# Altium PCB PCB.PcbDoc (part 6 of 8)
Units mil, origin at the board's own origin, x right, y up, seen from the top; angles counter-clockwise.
Board outline 11229.24 x 7764.43 mil, 14 copper layers (Top Layer, GND1, Signal 1, GND2, Signal 2, GND3, Singal 3, Power 1, GND4, Power 2, GND5, Power 3, GND6, Bottom Layer), stack 91.892 mil thick; 877 components, 305 nets, 2660 pads, 2851 vias.
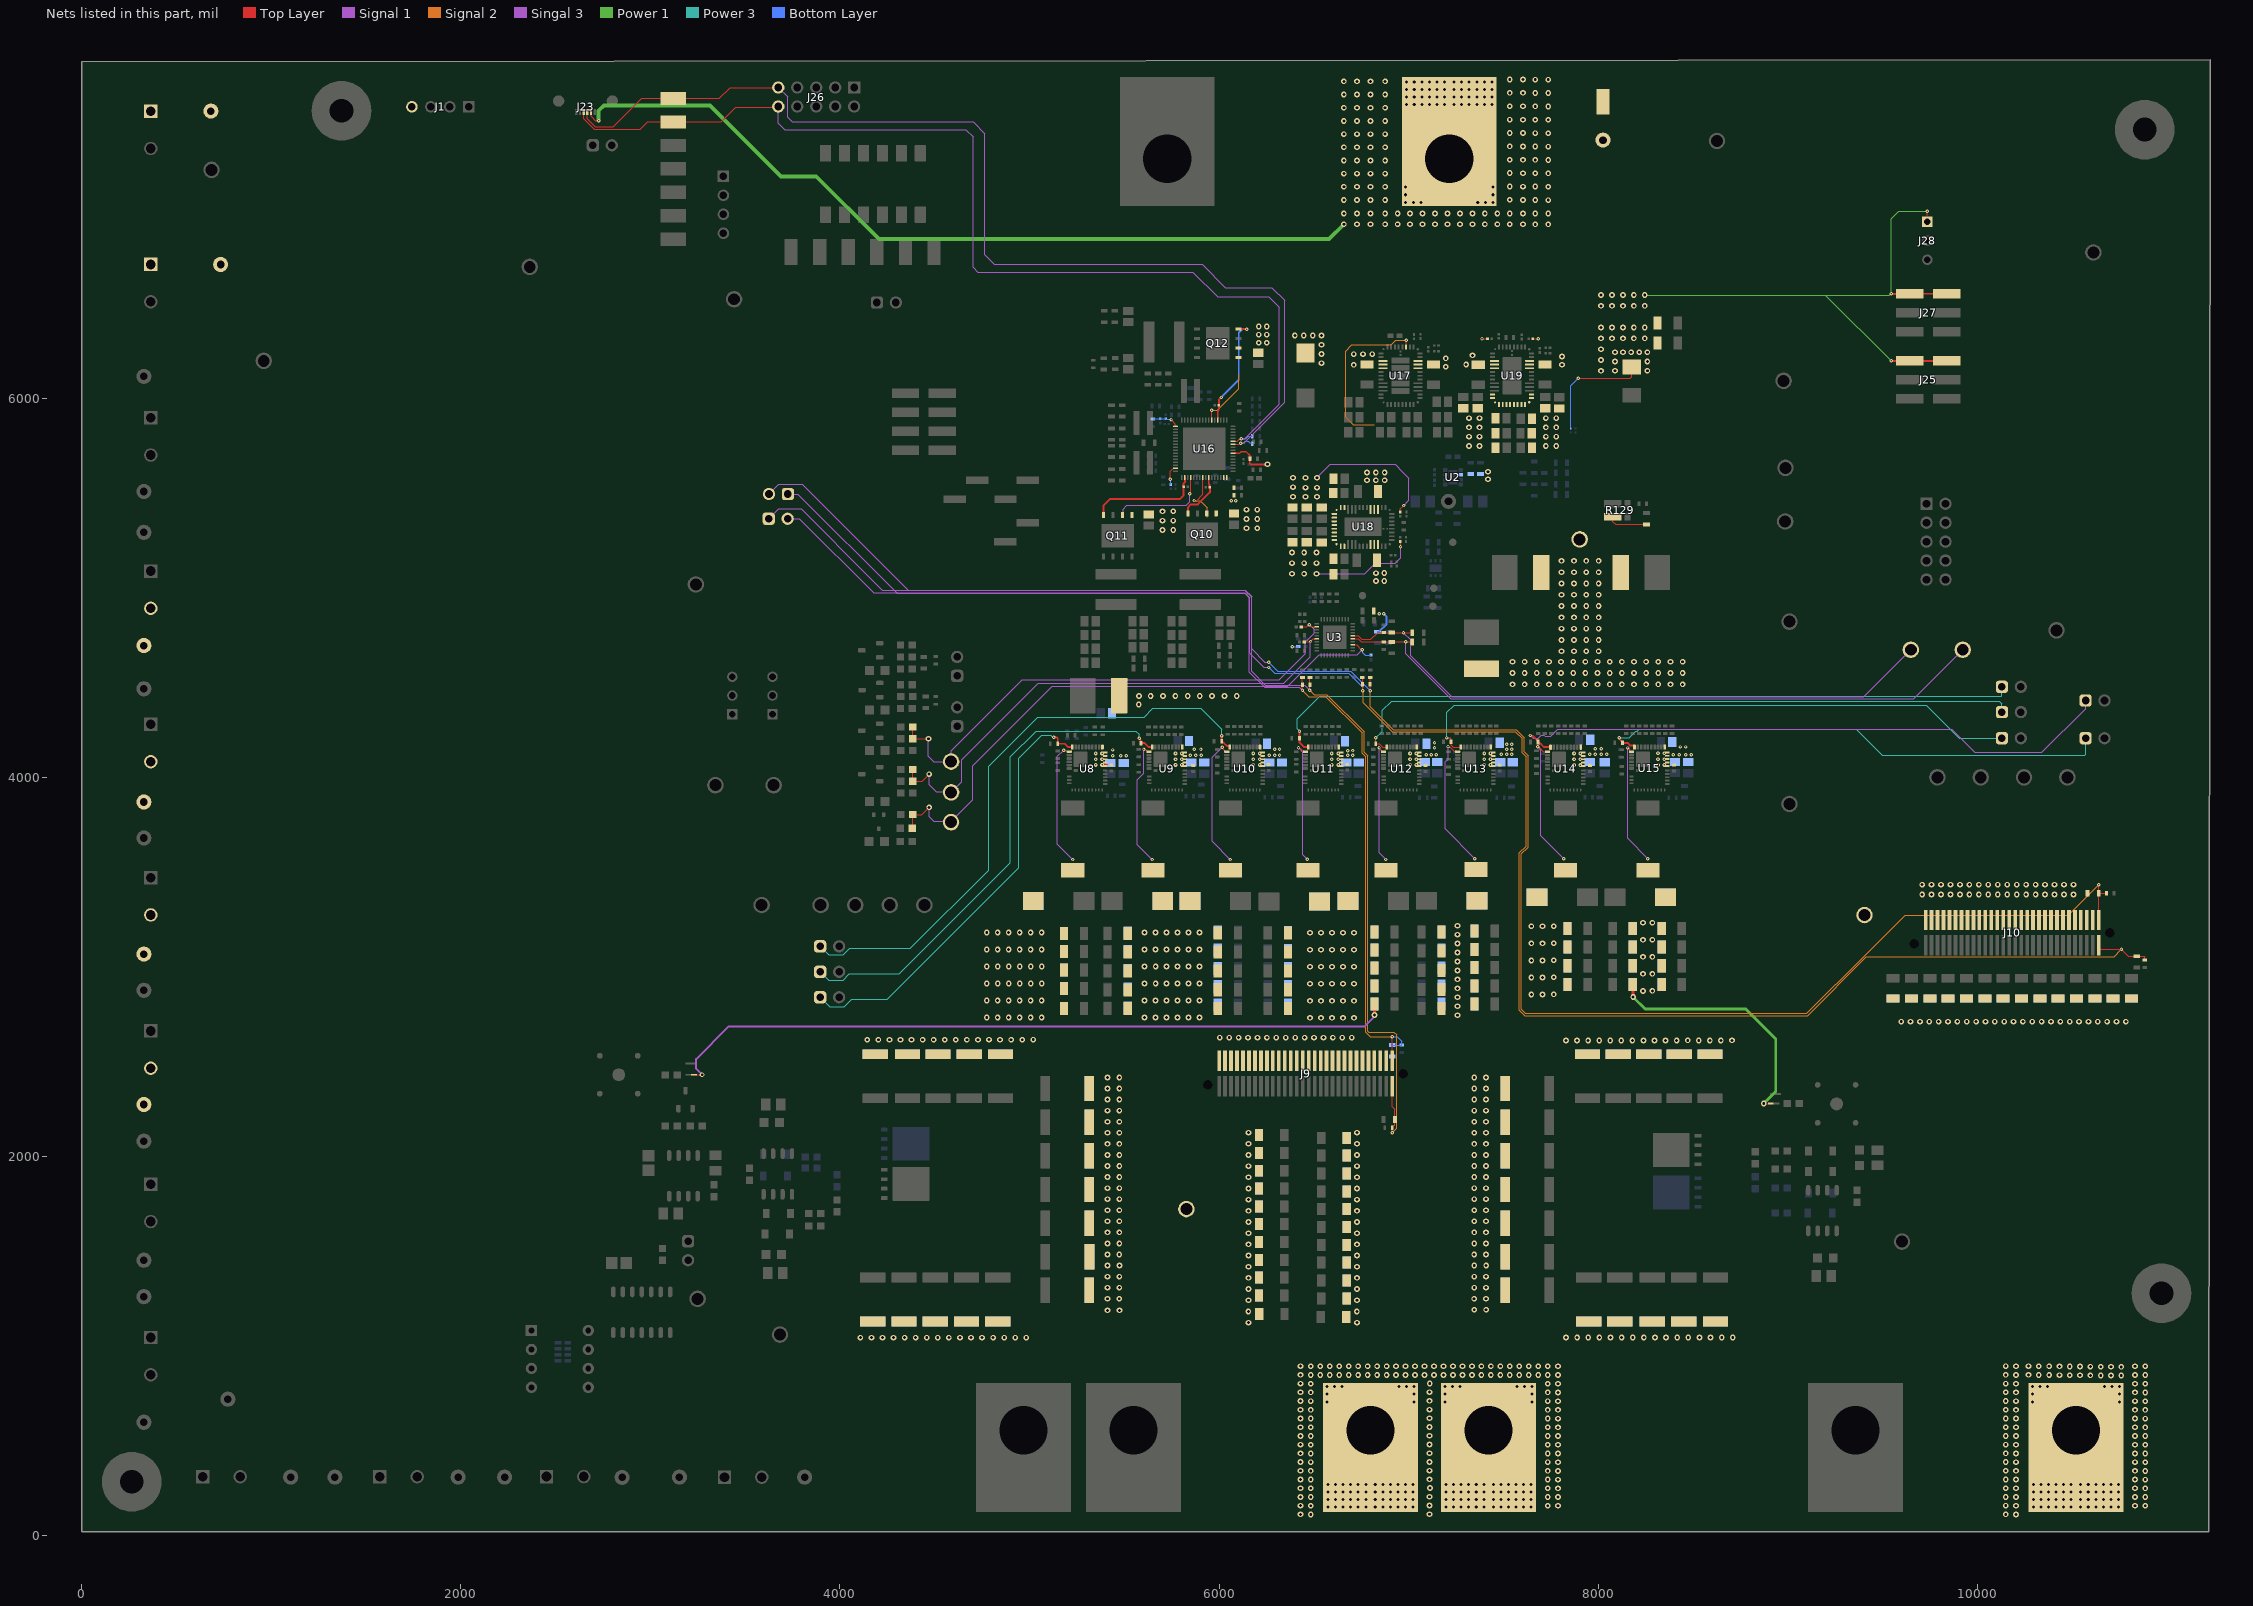
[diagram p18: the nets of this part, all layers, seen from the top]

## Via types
v1: diameter 30, hole 15, Top Layer to Bottom Layer, 1251 vias
v2: diameter 18, hole 8, Top Layer to Bottom Layer, tented both sides, 472 vias
v3: diameter 32, hole 16, Top Layer to Bottom Layer, 464 vias
v4: diameter 30, hole 15, Top Layer to Bottom Layer, tented both sides, 326 vias
v5: diameter 19.68, hole 7.87, Top Layer to Bottom Layer, 323 vias
v6: diameter 26, hole 12, Top Layer to Bottom Layer, tented both sides, 12 vias
v7: diameter 14, hole 6, Top Layer to Bottom Layer, tented both sides, 2 vias
v8: diameter 18, hole 8, Top Layer to Bottom Layer, 1 vias

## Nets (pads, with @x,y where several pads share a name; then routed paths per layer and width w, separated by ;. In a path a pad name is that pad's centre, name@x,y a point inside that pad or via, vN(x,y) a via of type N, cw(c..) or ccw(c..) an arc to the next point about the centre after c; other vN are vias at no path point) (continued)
PVOUT_A: C32.1 C33.1 C34.1 C35.1 C36.1 C37.1 C38.1 C39.1 C40.1 C41.1 C42.1 C43.1 C44.1 C45.1 C46.1 C47.1 C48.1 C49.1 C50.1 C51.1 C52.1 C53.1 C54.1 C55.1 C56.1 C57.1 C58.1 C59.1 C60.1 C61.1 C62.1 C63.1 C64.1 C65.1 C66.1 C67.1 C68.1 C69.1 C70.1 C71.1 C72.1 C73.1 C74.1 C75.1 C76.1 C77.1 C78.1 C79.1 C80.1 C81.1 C89.1 C90.1 C91.1 C92.1 C93.1 C94.1 C95.1 C96.1 C97.1 C98.1 C99.1 C100.1 C101.1 C102.1 C103.1 C104.1 C105.1 C106.1 C107.1 C108.1 C109.1 C110.1 C111.1 C112.1 C113.1 C114.1 C115.1 C116.1 C117.1 C118.1 C119.1 C120.1 C121.1 C122.1 C123.1 C124.1 C125.1 C126.1 C172.1 C173.1 C174.1 C175.1 C176.1 C177.1 C188.1 C189.1 C190.1 C191.1 C192.1 C193.1 C204.1 C205.1 C206.1 C207.1 C208.1 C209.1 C220.1 C221.1 C222.1 C223.1 C224.1 C225.1 C236.1 C237.1 C238.1 C239.1 C240.1 C241.1 C252.1 C253.1 C254.1 C255.1 C256.1 C257.1 J9.123 J9.125 J9.127 J9.129 J9.131 J9.133 J9.135 J9.137 J9.139 J9.141 J9.143 J9.145 J9.147 J9.149 J9.151 J9.153 J9.155 J9.157 J9.159 J9.161 J9.163 J9.165 J9.167 J9.169 J9.171 J9.173 J9.175 J9.177 J9.179 L2.2 L3.2 L4.2 L5.2 L6.2 L7.2 NT3.1 R8.2 R39.2 R40.2 R41.2 R42.2 R44.2 R45.2 R46.2 R47.2 R48.2 R49.2 R50.2 R51.2 R52.2 R53.2 R54.2 R55.2 R56.2 R57.2 R58.2 R59.2 R60.2 R61.2 R62.2 R63.2 R64.2 R65.2 R66.2 R67.2 R68.2 R69.2 R70.2 R71.2 R72.2 R73.2 R82.2 R83.2 R86.2 R87.2 R88.2 R89.2 R90.2 R91.2 R92.2 R93.2 R94.2 R95.2 R96.2 R97.2 R98.2 R99.2 R100.2 R101.2 R102.2 R103.2 R104.2 R105.2 R106.2 R107.2 R108.2 R109.2 R110.2 R111.2 R112.2 R113.2 R114.2 R115.2 R125.2 R126.2 T3.1 T4.1 TP19.1 U8.1 U9.1 U10.1 U11.1 U12.1 U13.1 | length 7901.4
  Top Layer w6: NT3.1@3230.02,2430.69 v6(3273.18,2430.69) ; v2(5180.06,4143.5) 5182.36,4141.2 5194.77,4141.2 5197.98,4137.99 5206.36,4137.99 U8.1@5209.67,4134.68 ; v2(5603.9,4147.12) 5606.19,4144.83 5613.37,4144.83 5623.52,4134.68 U9.1@5630.91,4134.68 ; v2(6017.35,4158.9) 6019.64,4156.6 6019.64,4149.21 6034.18,4134.68 U10.1@6041.07,4134.68 ; v2(6419.17,4155.89) 6421.46,4153.6 6429.65,4153.6 6448.57,4134.68 U11.1@6455.46,4134.68 ; v2(6843.92,4154.66) 6843.92,4152.5 6861.74,4134.68 U12.1@6868.12,4134.68 ; v2(7207.85,4159.99) 7210.15,4157.69 7220.28,4157.69 7241.51,4136.47 7257.02,4136.47 U13.1@7258.81,4134.68
  Top Layer w15: v4(6819.59,2746.04) C240.1@6819.59,2803.92
  Signal 1 w6: v2(5180.06,4143.5) 5146.3,4109.74 5146.3,3647.9 v2(5228.1,3566.1) ; v2(5603.9,4147.12) 5603.9,4021.47 5569.38,3986.95 5569.38,3644.38 v2(5647.66,3566.1) ; v2(6017.35,4158.9) 5963.22,4104.77 5963.22,3661.48 v2(6058.6,3566.1) ; v2(6419.17,4155.89) 6441.86,4133.2 6441.86,3590.6 v2(6465.52,3566.94) ; v2(6843.92,4154.66) 6843.92,3602.55 v2(6880.18,3566.29) ; v2(7207.85,4159.99) 7207.85,4096.23 7192.4,4080.78 7192.4,3727.89 v2(7349.89,3570.41)
  Signal 1 w10: v6(3273.18,2430.69) 3241.2,2462.66 3241.2,2513.5 3411.9,2684.2 6766.82,2684.2 6815.76,2733.14 6815.76,2742.21 v4(6819.59,2746.04)
  other v1: 6429.5,111.4 6483.9,111 7110.2,112.2 6429.5,157.39 6483.9,156.99 7734,156.99 7788.4,156.59 7110.2,158.19 6429.5,203.39 6483.9,202.99 7734,202.99 7788.4,202.59 7110.2,204.19 6429.5,249.38 6483.9,248.98 7734,248.98 7788.4,248.58 7112.6,250.18 6429.5,295.38 6483.9,294.97 7734,294.97 7788.4,294.57 7110.2,296.18 6429.5,341.37 6483.9,340.97 7734,340.97 7788.4,340.57 7110.2,342.17 6429.5,387.36 6483.9,386.96 7734,386.96 7788.4,386.56 7110.2,388.16 6429.5,433.36 6483.9,432.96 7734,432.96 7788.4,432.56 7110.2,434.16 6429.5,479.35 6483.9,478.95 7734,478.95 7788.4,478.55 7110.6,480.15 6429.5,525.34 6483.9,524.94 7734,524.94 7788.4,524.54 7110.2,526.14 6429.5,571.34 6483.9,570.94 7734,570.94 7788.4,570.54 7110.2,572.14 6429.5,617.33 6483.9,616.93 7734,616.93 7788.4,616.53 7110.2,618.13 6429.5,663.33 6483.9,662.92 7734,662.92 7788.4,662.52 7110.2,664.13 6429.5,709.32 6483.9,708.92 7734,708.92 7788.4,708.52 7110.2,710.12 6429.5,755.31 6483.9,754.91 7734,754.91 7788.4,754.51 7110.2,756.11 6429.5,801.31 6483.9,800.91 7734,800.91 7788.4,800.5 7111.3,802.11 7788.4,846.5 6429.5,847.3 6483.9,846.9 6533.9,846.9 6583.91,846.9 6633.91,846.9 6683.92,846.9 6733.92,846.9 6783.92,846.9 6833.93,846.9 6883.93,846.9 6933.94,846.9 6983.94,846.9 7033.94,846.9 7083.95,846.9 7133.95,846.9 7183.96,846.9 7233.96,846.9 7283.96,846.9 7333.97,846.9 7383.97,846.9 7433.98,846.9 7483.98,846.9 7533.98,846.9 7583.99,846.9 7633.99,846.9 7684,846.9 7734,846.9 7788.4,892.49 6429.5,893.29 6483.9,892.89 6533.9,892.89 6583.91,892.89 6633.91,892.89 6683.92,892.89 6733.92,892.89 6783.92,892.89 6833.93,892.89 6883.93,892.89 6933.94,892.89 6983.94,892.89 7033.94,892.89 7083.95,892.89 7133.95,892.89 7183.96,892.89 7233.96,892.89 7283.96,892.89 7333.97,892.89 7383.97,892.89 7433.98,892.89 7483.98,892.89 7533.98,892.89 7583.99,892.89 7633.99,892.89 7684,892.89 7734,892.89 4107.7,1043.9 4166.06,1043.9 4224.43,1043.9 4282.79,1043.9 4341.15,1043.9 4399.51,1043.9 4457.88,1043.9 4516.24,1043.9 4574.6,1043.9 4632.96,1043.9 4691.33,1043.9 4749.69,1043.9 4808.05,1043.9 4866.41,1043.9 4924.78,1043.9 4983.14,1043.9 7830.4,1044.2 7889.06,1044.2 7947.72,1044.2 8006.38,1044.2 8065.04,1044.2 8123.69,1044.2 8182.35,1044.2 8241.01,1044.2 8299.67,1044.2 8358.33,1044.2 8416.99,1044.2 8475.65,1044.2 8534.31,1044.2 8592.97,1044.2 8651.62,1044.2 8710.28,1044.2 6155.4,1123.08 6727.7,1123.08 6154.7,1182.04 6727,1182.04 5411.9,1187.7 5474.4,1187.7 7346.4,1190.69 7408.9,1190.69 6155,1241.01 6727.3,1241.01 5411.2,1249.05 5473.7,1249.05 7345.7,1249.05 7408.2,1249.05 6155,1299.97 6727.3,1299.97 5411.5,1307.41 5474,1307.41 7346,1307.41 7408.5,1307.41 6155,1358.93 6727.3,1358.93 5411.5,1365.77 5474,1365.77 7346,1365.77 7408.5,1365.77 6155,1417.9 6727.3,1417.9 5411.9,1424.14 5474.4,1424.14 7346.4,1424.14 7408.9,1424.14 6155,1476.86 6727.3,1476.86 5411.2,1482.5 5473.7,1482.5 7345.7,1482.5 7408.2,1482.5 6155,1535.82 6727.3,1535.82 5411.5,1540.86 5474,1540.86 7346,1540.86 7408.5,1540.86 6155,1594.79 6727.3,1594.79 5411.5,1599.22 5474,1599.22 7346,1599.22 7408.5,1599.22 6155,1653.75 6727.3,1653.75 5411.5,1657.59 5474,1657.59 7346,1657.59 7408.5,1657.59 6155,1712.71 6727.3,1712.71 5411.5,1715.95 5474,1715.95 7346,1715.95 7408.5,1715.95 6155,1771.68 6727.3,1771.68 5411.5,1774.31 5474,1774.31 7346,1774.31 7408.5,1774.31 6155,1830.64 6727.3,1830.64 5411.5,1832.67 5474,1832.67 7346,1832.67 7408.5,1832.67 6155,1889.6 6727.3,1889.6 5411.5,1891.04 5474,1891.04 7346,1891.04 7408.5,1891.04 5411.5,1949.4 5474,1949.4 6155,1948.57 6727.3,1948.57 7346,1949.4 7408.5,1949.4 5411.5,2007.76 5474,2007.76 6155,2007.53 6727.3,2007.53 7346,2007.76 7408.5,2007.76 5411.5,2066.12 5474,2066.12 6155,2066.5 6727.3,2066.5 7346,2066.12 7408.5,2066.12 5411.5,2124.49 5474,2124.49 7346,2124.49 7408.5,2124.49 6155,2125.46 6727.3,2125.46 5411.5,2182.85 5474,2182.85 7346,2182.85 7408.5,2182.85 5411.5,2241.21 5474,2241.21 7346,2241.21 7408.5,2241.21 5411.5,2299.57 5474,2299.57 7346,2299.57 7408.5,2299.57 5411.5,2357.94 5474,2357.94 7346,2357.94 7408.5,2357.94 5411.5,2416.3 5474,2416.3 7346,2416.3 7408.5,2416.3 8414.03,2611.3 8647.48,2611.3 7830.4,2611.6 7888.76,2611.6 7947.13,2611.6 8005.49,2611.6 8063.85,2611.6 8122.21,2611.6 8180.58,2611.6 8238.94,2611.6 8297.3,2611.6 8355.66,2611.6 8472.39,2612 8530.75,2611.6 8589.11,2611.6 8705.84,2612 4727.93,2615.2 4961.38,2615.2 4144.3,2615.5 4202.66,2615.5 4261.03,2615.5 4319.39,2615.5 4377.75,2615.5 4436.11,2615.5 4494.48,2615.5 4552.84,2615.5 4611.2,2615.5 4669.56,2615.5 4786.29,2615.9 4844.65,2615.5 4903.01,2615.5 5019.74,2615.9 6003.7,2626.37 6053.44,2626.37 6103.17,2626.37 6152.91,2626.37 6202.65,2626.37 6252.39,2626.37 6302.12,2626.37 6351.86,2626.37 6401.6,2626.37 6451.33,2626.37 6501.07,2626.37 6550.81,2626.37 6600.55,2626.37 6650.28,2626.37 6700.02,2626.37 4774.1,2732.69 4832.1,2732.69 4890.1,2732.69 7257.48,2744.81 7257.48,2792.03 6479.66,2820.58 6537.66,2820.58 6595.66,2820.58 6653.66,2820.58 6711.93,2820.58 4774.1,2822.45 4832.1,2822.45 4890.1,2822.45 5006.1,2822.45 5064.1,2822.45 5606.97,2822.45 5664.97,2822.45 5722.97,2822.45 5780.97,2822.45 5838.97,2822.45 5896.97,2822.45 7257.48,2839.26 7257.48,2886.48 6479.66,2910.34 6537.93,2910.34 6595.93,2910.34 6653.93,2910.34 6711.93,2910.34 4774.1,2912.22 4832.37,2912.22 4890.37,2912.22 5006.37,2912.22 5064.37,2912.22 5606.97,2912.22 5665.25,2912.22 5723.25,2912.22 5781.25,2912.22 5839.25,2912.22 5897.25,2912.22 7257.48,2933.71 7257.48,2980.93 6479.66,3000.11 6537.93,3000.11 6595.93,3000.11 6653.93,3000.11 6711.93,3000.11 4774.1,3001.98 4832.37,3001.98 4890.37,3001.98 5006.37,3001.98 5064.37,3001.98 5606.97,3001.98 5665.25,3001.98 5723.25,3001.98 5781.25,3001.98 5839.25,3001.98 5897.25,3001.98 7257.48,3028.16 7257.48,3075.38 6479.66,3089.87 6537.66,3089.87 6595.66,3089.87 6653.66,3089.87 6711.93,3089.87 4774.1,3091.75 4832.1,3091.75 4890.1,3091.75 5006.1,3091.75 5064.1,3091.75 5606.97,3091.75 5664.97,3091.75 5722.97,3091.75 5780.97,3091.75 5838.97,3091.75 5896.97,3091.75 7257.48,3122.61 7257.48,3169.83 6479.66,3179.64 6537.66,3179.64 6595.66,3179.64 6653.66,3179.64 6711.93,3179.64 4774.1,3181.51 4832.1,3181.51 4890.1,3181.51 5006.1,3181.51 5064.1,3181.51 5606.97,3181.51 5664.97,3181.51 5722.97,3181.51 5780.97,3181.51 5838.97,3181.51 5896.97,3181.51 7257.48,3217.06
  other v3: 6574,150.2 6614,150.2 6654,150.2 6694,150.2 6734,150.2 6774,150.2 6824,150.2 6864,150.2 6904,150.2 6944,150.2 6984,150.2 7024,150.2 7196.9,150.2 7236.9,150.2 7276.9,150.2 7316.9,150.2 7356.9,150.2 7396.9,150.2 7446.9,150.2 7486.9,150.2 7526.9,150.2 7566.9,150.2 7606.9,150.2 7646.9,150.2 6574,190.2 6614,190.2 6654,190.2 6694,190.2 6734,190.2 6774,190.2 6824,190.2 6864,190.2 6904,190.2 6944,190.2 6984,190.2 7024,190.2 7196.9,190.2 7236.9,190.2 7276.9,190.2 7316.9,190.2 7356.9,190.2 7396.9,190.2 7446.9,190.2 7486.9,190.2 7526.9,190.2 7566.9,190.2 7606.9,190.2 7646.9,190.2 6574,230.2 6614,230.2 6654,230.2 6694,230.2 6734,230.2 6774,230.2 6824,230.2 6864,230.2 6904,230.2 6944,230.2 6984,230.2 7024,230.2 7196.9,230.2 7236.9,230.2 7276.9,230.2 7316.9,230.2 7356.9,230.2 7396.9,230.2 7446.9,230.2 7486.9,230.2 7526.9,230.2 7566.9,230.2 7606.9,230.2 7646.9,230.2 6574,270.2 6614,270.2 6654,270.2 6694,270.2 6734,270.2 6774,270.2 6824,270.2 6864,270.2 6904,270.2 6944,270.2 6984,270.2 7024,270.2 7196.9,270.2 7236.9,270.2 7276.9,270.2 7316.9,270.2 7356.9,270.2 7396.9,270.2 7446.9,270.2 7486.9,270.2 7526.9,270.2 7566.9,270.2 7606.9,270.2 7646.9,270.2 6569,705.2 7029,705.2 7191.9,705.2 7651.9,705.2 6569,745.2 7029,745.2 7191.9,745.2 7651.9,745.2 6569,785.2 6609,785.2 6649,785.2 6949,785.2 6989,785.2 7029,785.2 7191.9,785.2 7231.9,785.2 7271.9,785.2 7571.9,785.2 7611.9,785.2 7651.9,785.2
  other v4: 6479.66,2730.81 6537.66,2730.81 6595.66,2730.81 6653.66,2730.81 6711.93,2730.81 4948.1,2732.69 5006.1,2732.69 5064.1,2732.69 5606.97,2732.69 5664.97,2732.69 5722.97,2732.69 5780.97,2732.69 5838.97,2732.69 5896.97,2732.69 4948.1,2822.45 4948.37,2912.22 4948.37,3001.98 4948.1,3091.75 4948.1,3181.51
PVOUT_B: C127.1 C128.1 C129.1 C130.1 C131.1 C132.1 C133.1 C134.1 C135.1 C136.1 C137.1 C138.1 C139.1 C140.1 C141.1 C142.1 C143.1 C144.1 C145.1 C146.1 C147.1 C148.1 C149.1 C150.1 C151.1 C152.1 C153.1 C154.1 C155.1 C156.1 C157.1 C158.1 C159.1 C160.1 C161.1 C162.1 C163.1 C164.1 C165.1 C166.1 C167.1 C168.1 C169.1 C170.1 C268.1 C269.1 C270.1 C271.1 C272.1 C273.1 C284.1 C285.1 C286.1 C287.1 C288.1 C289.1 J10.123 J10.125 J10.127 J10.129 J10.131 J10.133 J10.135 J10.137 J10.139 J10.141 J10.143 J10.145 J10.147 J10.149 J10.151 J10.153 J10.155 J10.157 J10.159 J10.161 J10.163 J10.165 J10.167 J10.169 J10.171 J10.173 J10.175 J10.177 J10.179 L8.2 L9.2 NT4.1 R10.2 T7.1 TP20.1 U14.1 U15.1 | length 2686.9
  Top Layer w6: v2(7680.76,4160.06) 7683.06,4157.77 7688.04,4157.77 7711.53,4134.28 U14.1@7732.9,4134.28 ; v2(8155.1,4154.5) 8165.71,4143.89 8165.71,4138.81 8169.72,4134.81 U15.1@8177.17,4134.81 ; v1(8873.28,2278.57) NT4.1@8910.61,2278.57
  Top Layer w15: C147.1@8183,2907.17 8183.84,2906.33 8183.84,2841.28 v1(8184.67,2840.44)
  Signal 1 w6: v2(7680.76,4160.06) 7697.2,4143.63 7697.2,3692.72 v2(7819.51,3570.41) ; v2(8155.1,4154.5) 8155.1,3677.85 v2(8262.53,3570.41)
  Power 1 w15: v1(8184.67,2840.44) 8248.22,2776.9 8778.6,2776.9 8936.8,2618.7 8936.8,2342.08 v1(8873.28,2278.57)
  other v1: 10150.2,111.4 10204.6,111 10150.2,157.39 10204.6,156.99 10831.8,156.99 10886.2,156.59 10150.2,203.39 10204.6,202.99 10831.8,202.99 10886.2,202.59 10150.2,249.38 10204.6,248.98 10831.8,248.98 10886.2,248.58 10150.2,295.38 10204.6,294.97 10831.8,294.97 10886.2,294.57 10150.2,341.37 10204.6,340.97 10831.8,340.97 10886.2,340.57 10150.2,387.36 10204.6,386.96 10831.8,386.96 10886.2,386.56 10150.2,433.36 10204.6,432.96 10831.8,432.96 10886.2,432.56 10150.2,479.35 10204.6,478.95 10831.8,478.95 10886.2,478.55 10150.2,525.34 10204.6,524.94 10831.8,524.94 10886.2,524.54 10150.2,571.34 10204.6,570.94 10831.8,570.94 10886.2,570.54 10150.2,617.33 10204.6,616.93 10831.8,616.93 10886.2,616.53 10150.2,663.33 10204.6,662.92 10831.8,662.92 10886.2,662.52 10150.2,709.32 10204.6,708.92 10831.8,708.92 10886.2,708.52 10150.2,755.31 10204.6,754.91 10831.8,754.91 10886.2,754.51 10150.2,801.31 10204.6,800.91 10831.8,800.91 10886.2,800.5 10651,844.49 10705.4,844.09 10759.8,843.69 10542.2,845.29 10596.6,844.89 10379,846.5 10433.4,846.1 10487.8,845.7 10886.2,846.5 10150.2,847.3 10204.6,846.9 10270.2,847.3 10324.6,846.9 10831.8,846.9 10651,890.49 10705.4,890.09 10759.8,889.68 10542.2,891.29 10596.6,890.89 10379,892.49 10433.4,892.09 10487.8,891.69 10886.2,892.49 10150.2,893.29 10204.6,892.89 10270.2,893.29 10324.6,892.89 10831.8,892.89 9598.76,2711.03 9648.14,2711.03 9697.52,2711.03 9746.9,2711.03 9796.28,2711.03 9845.66,2711.03 9895.04,2711.03 9944.42,2711.03 9993.8,2711.03 10043.18,2711.03 10092.56,2711.03 10141.94,2711.03 10191.32,2711.03 10240.7,2711.03 10290.08,2711.03 10339.46,2711.03 10388.84,2711.03 10438.22,2711.03 10487.6,2711.03 10536.98,2711.03 10586.36,2711.03 10635.74,2711.03 10685.12,2711.03 10734.5,2711.03 10783.88,2711.03 7647.7,2854.27 7706.6,2854.27 7765.5,2854.87 8236.73,2872.92 8285.79,2873.15 7647.7,2944.03 7706.74,2944.03 7765.77,2944.63 8236.73,2962.68 8285.92,2962.92 7647.7,3033.8 7706.74,3033.8 7765.77,3034.4 8236.73,3052.45 8285.92,3052.68 7647.7,3123.56 7706.6,3123.56 7765.5,3124.16 8236.73,3142.21 8285.79,3142.45 7647.7,3213.93 7706.6,3213.93 7765.5,3213.93 8236.73,3232.58 8285.79,3232.81 9708.94,3381.13 9758.85,3381.13 9808.76,3381.13 9858.67,3381.13 9908.58,3381.13 9958.49,3381.13 10008.4,3381.13 10058.32,3381.13 10108.23,3381.13 10158.14,3381.13 10208.05,3381.13 10257.96,3381.13 10307.87,3381.13 10357.78,3381.13 10407.69,3381.13 10457.61,3381.13 10507.52,3381.13 9708.94,3433.66 9758.85,3433.66 9808.76,3433.66 9858.67,3433.66 9908.58,3433.66 9958.49,3433.66 10008.4,3433.66 10058.32,3433.66 10108.23,3433.66 10158.14,3433.66 10208.05,3433.66 10257.96,3433.66 10307.87,3433.66 10357.78,3433.66 10407.69,3433.66 10457.61,3433.66 10507.52,3433.66
  other v3: 10295.5,150.2 10335.5,150.2 10375.5,150.2 10415.5,150.2 10455.5,150.2 10495.5,150.2 10545.5,150.2 10585.5,150.2 10625.5,150.2 10665.5,150.2 10705.5,150.2 10745.5,150.2 10295.5,190.2 10335.5,190.2 10375.5,190.2 10415.5,190.2 10455.5,190.2 10495.5,190.2 10545.5,190.2 10585.5,190.2 10625.5,190.2 10665.5,190.2 10705.5,190.2 10745.5,190.2 10295.5,230.2 10335.5,230.2 10375.5,230.2 10415.5,230.2 10455.5,230.2 10495.5,230.2 10545.5,230.2 10585.5,230.2 10625.5,230.2 10665.5,230.2 10705.5,230.2 10745.5,230.2 10295.5,270.2 10335.5,270.2 10375.5,270.2 10415.5,270.2 10455.5,270.2 10495.5,270.2 10545.5,270.2 10585.5,270.2 10625.5,270.2 10665.5,270.2 10705.5,270.2 10745.5,270.2 10290.5,705.2 10750.5,705.2 10290.5,745.2 10750.5,745.2 10290.5,785.2 10330.5,785.2 10370.5,785.2 10670.5,785.2 10710.5,785.2 10750.5,785.2
RS-: NT7.1 U17.41 | length 894.2
  Top Layer w6: U17.41@6986.72,6269.66 v2(6986.72,6305.12)
  Signal 2 w6: NT7.1@6817.7,5859.51 6707.45,5859.51 6667.1,5899.86 6667.1,6248.03 6700.8,6281.74 6909.14,6281.74 6932.52,6305.12 v2(6986.72,6305.12)
SCL: J23.3 J26.9 R226.1 TP78.1 U16.58 | length 5692.1
  Top Layer w6: J23.3@2667.54,7508.58 2667.54,7473.79 2710.03,7431.3 2803.5,7431.3 2953.5,7581.3 TP78.1@3120.11,7581.3 3364,7581.3 3421.4,7638.7 J26.9@3674.8,7638.7 ; U16.58@6073.37,5756.07 6105.12,5756.07 6111.83,5762.78 v2(6115.08,5762.78)
  Singal 3 w6: J26.9@3674.8,7638.7 3724.5,7589 3724.5,7480.8 3748,7457.3 4702.1,7457.3 4763.8,7395.6 4763.8,6755.6 4813.8,6705.6 5911.9,6705.6 6033.9,6583.6 6278.6,6583.6 6346.66,6515.54 6346.66,5978.06 6132.07,5763.46 6115.76,5763.46 v2(6115.08,5762.78)
  Bottom Layer w6: v2(6115.08,5762.78) 6129.1,5762.78 6137.93,5771.62 6154.29,5771.62 6161.81,5764.1 6170.3,5764.1 6174.8,5759.6 R226.1@6174.8,5759.5
SDA: J23.4 J26.10 R227.1 TP79.1 U16.59 | length 5570.8
  Top Layer w6: J23.4@2647.86,7508.58 2647.86,7474.59 2705.07,7417.38 2947.38,7417.38 2987.38,7457.38 TP79.1@3120.11,7457.38 3372.68,7457.38 3451,7535.7 3671.8,7535.7 J26.10@3674.8,7538.7 ; U16.59@6073.37,5771.82 6096.15,5771.82 6107.67,5783.34 6115.37,5783.34 v2(6117.67,5785.64)
  Singal 3 w6: J26.10@3674.8,7538.7 3674.8,7450.7 3708.6,7416.9 4665,7416.9 4703.4,7378.5 4703.4,6689.7 4728.1,6665 5862.12,6665 5993.26,6533.86 6262.94,6533.86 6318,6478.8 6318,5969.15 6134.49,5785.64 v2(6117.67,5785.64)
  Bottom Layer w6: v2(6117.67,5785.64) 6139.91,5785.64 6153.27,5799 R227.1@6174.8,5799
SNS1: NT9.1 U16.36 | length 540.7
  Top Layer w6: v2(5845.37,5496) 5845.37,5499.25 5850.92,5504.8 U16.36@5850.92,5580.87
  Singal 3 w6: NT9.1@5493.3,5372 5493.3,5415.14 5512.06,5433.9 5825.69,5433.9 5845.37,5453.58 v2(5845.37,5496)
SNS2: NT11.1 U16.6 | length 318.8
  Top Layer w6: U16.6@5961.16,5884.02 v2(5961.16,5935.53)
  Signal 2 w6: v2(5961.16,5935.53) 5990.64,5935.53 6103.7,6048.59 NT11.1@6103.7,6126.5
SNS6: NT19.1 U16.40 | length 283.7
  Top Layer w6: v2(5868,5459.9) 5881.95,5459.9 5913.92,5491.87 U16.40@5913.92,5580.87
  Signal 2 w6: v2(5868,5459.9) 5899.82,5459.9 5937.93,5421.79 NT19.1@5937.93,5372
SW1: C308.2 Q11.4 U16.34 | length 591
  Top Layer w10: Q11.4@5390.35,5384.05 5390.35,5433.55 5425.82,5469.02 5795.4,5469.02 5813.13,5486.75 5813.13,5550.43 5819.43,5556.73 U16.34@5819.43,5580.87
SW2: C318.2 Q12.4 U16.4 | length 602.2
  Top Layer w6: Q12.4@6103.3,6364.17 Q12.4@6103.4,6364.27 ; v2@6146.63,6364.27 v2(6146.73,6364.37)
  Top Layer w8: U16.4@5992.66,5884.02 5992.66,5930.81 5998.96,5937.11 C318.2@5998.96,5963.43
  Top Layer w10: C318.2@5998.96,5963.43 5998.96,5990.79 6011.5,6003.33 v2(6011.5,6003.7) ; Q12.4@6103.4,6364.27 v2@6146.63,6364.27
  Bottom Layer w10: v2(6011.5,6003.7) 6103.7,6095.9 6103.7,6346.23 6121.84,6364.37 v2(6146.73,6364.37)
SW6: C300.2 Q10.4 U16.42 | length 261.8
  Top Layer w10: Q10.4@5835.18,5391.85 5835.18,5422.98 5851.6,5439.4 5888.52,5439.4 5951.71,5502.6 C300.2@5951.71,5529.9 5951.21,5529.9 5949.91,5531.2 5949.91,5542.69 5945.41,5547.19 U16.42@5945.41,5580.87
SWA1: C356.1 J1.4 U16.31 | length 103.8
  Top Layer w6: v2(5742.64,5572.45) 5742.64,5613.48 5755.43,5626.28 5756.06,5626.28 5759.87,5630.09 U16.31@5770.22,5630.09
  Bottom Layer w6: v2(5742.64,5572.45) 5744.51,5570.57 C356.1@5744.51,5544.9
TSENA: C22.1 R27.1 R37.2 TP11.1 U3.35 | length 3566.3
  Top Layer w6: U3.35@6704.62,4730.39 6734.78,4730.39 6750.97,4714.2 C22.1@6868.12,4714.2 R37.2@6911.89,4714.2 6912.64,4714.95 6984.82,4714.95 v2(6985.13,4714.64) 7018.48,4714.64 R27.1@7019.59,4713.53
  Singal 3 w6: v2(6985.13,4714.64) 6985.13,4650.67 7222.44,4413.36 9664.04,4413.36 TP11.1@9948.68,4698
TSENB: C21.1 R25.1 R33.2 TP12.1 U3.36 | length 3324.8
  Top Layer w6: U3.36@6704.62,4746.14 6734.59,4746.14 6753.82,4726.9 6800.24,4726.9 6836.48,4763.14 C21.1@6868.12,4763.14 R33.2@6911.63,4763.14 6912.53,4762.24 v2(6972.96,4762.24) 7018.7,4762.24 R25.1@7019.59,4763.14
  Singal 3 w6: v2(6972.96,4762.24) 7010.47,4724.73 7010.47,4640.88 7227,4424.36 9400.96,4424.36 TP12.1@9661.9,4685.3
VCCAUX: C346.1 C347.1 J31.1 R214.2 TP74.1 U16.17 | length 144
  Top Layer w6: v2(5746.62,5886.95) 5746.77,5886.95 5770.22,5863.5 U16.17@5770.22,5850.56
  Bottom Layer w6: R214.2@5651.14,5890.65 5662.3,5890.67 C346.1@5690.39,5890.73 C347.1@5718.5,5890.73 5720.39,5888.84 5744.72,5888.84 v2(5746.62,5886.95) ; R214.2@5662.3,5891.2 R214.2@5662.77,5890.73
VIN: C4.1 C87.1 C88.1 C299.1 C307.1 C317.1 C336.1 C348.1 C357.1 C358.1 C370.1 C371.1 C383.1 C384.1 J23.2 J25.1 J25.2 J27.1 J27.2 J28.1 L1.1 NT1.1 Q10.1 Q10.2 Q11.1 Q11.2 Q12.1 Q12.2 R4.2 T1.1 TP59.1 TP60.1 U2.2 U16.55 U17.4 U17.5 U17.6 U17.33 U17.34 U17.35 U18.4 U18.5 U18.6 U18.33 U18.34 U18.35 U19.4 U19.5 U19.6 U19.33 U19.34 U19.35 | length 8284.4
  Top Layer w6: J23.2@2687.23,7508.58 2687.23,7485.99 2708.59,7464.63 2725.69,7464.63 v2(2726.59,7463.74) ; v2(7893.89,6104.93) 8169.53,6104.93 8177.1,6112.5 L1.1@8177.1,6164.93 ; J28.1@9736.5,6930.2 v2(9736.5,6986.7)
  Top Layer w8: U16.55@6073.37,5708.83 6107.64,5708.83 6115.12,5716.31 6144.44,5716.31 6162.18,5698.57 6162.18,5679.55 C348.1@6162.47,5679.26 6162.47,5654.63 6167.11,5649.99 6254.29,5649.99 v4(6255.4,5651.1)
  Top Layer w10: v2(9546.3,6196.6) 9643.16,6196.6 J25.1@9643.46,6196.9 J25.2@9838.34,6196.9 ; v2(9546.3,6550.3) 9643.16,6550.3 J27.1@9643.46,6550.6 J27.2@9838.34,6550.6
  Power 1 w6: v4(8246.1,6543.9) 9199,6543.9 ; v2(9546.3,6196.6) 9199,6543.9 ; v2(9736.5,6986.7) 9587,6986.7 9546.3,6946 v2(9546.3,6550.3) 9543.19,6550.3 9536.79,6543.9 9199,6543.9
  Power 1 w20: v2(2726.59,7463.74) 2726.59,7515.9 2754.93,7544.25 3314.15,7544.25 3688.6,7169.8 3874.8,7169.8 4205.7,6838.9 6580,6838.9 v1(6658.6,6917.5)
  Bottom Layer w6: NT1.1@7855.14,5843.36 7855.14,6066.18 v2(7893.89,6104.93)
  other v1: 5701.8,5304.5 5758.06,5304.5 6145.14,5313.5 6201.4,5313.5 5701.8,5353.8 5758.06,5353.8 6145.14,5362.8 6201.4,5362.8 5701.8,5402.9 5758.06,5403.1 6145.14,5412.1 6201.4,5412.1 6780.81,5567.25 6827.18,5567.25 6873.54,5567.25 6780.81,5608.05 6827.18,5608.05 6873.54,5608.05 8015.22,6143.89 8015.22,6201.03 8088.52,6242.52 8131.3,6242.52 8174.08,6242.52 8216.87,6242.52 8259.65,6242.52 8015.22,6258.17 6209.72,6292.5 6251.42,6292.5 8015.22,6315.32 8072.94,6315.32 8130.66,6315.32 8188.38,6315.32 8246.1,6315.32 6209.72,6335.3 6251.42,6335.3 8015.22,6372.46 8072.94,6372.46 8130.66,6372.46 8188.38,6372.46 8246.1,6372.46 6209.72,6378.1 6251.42,6378.1 7667.8,6916.8 7737.1,6916.8 6727.9,6917.5 6799.35,6917.5 6876.17,6917.5 6941.94,6917.5 7007.71,6917.5 7073.49,6917.5 7139.26,6917.5 7205.03,6917.5 7270.81,6917.5 7336.58,6917.5 7402.35,6917.5 7468.13,6917.5 7533.9,6917.5 7603.2,6917.5 7667.8,6973.9 7737.1,6973.9 6658.6,6974.6 6727.9,6974.6 6799.35,6974.6 6876.17,6974.6 6941.94,6974.6 7007.71,6974.6 7073.49,6974.6 7139.26,6974.6 7205.03,6974.6 7270.81,6974.6 7336.58,6974.6 7402.35,6974.6 7468.13,6974.6 7533.9,6974.6 7603.2,6974.6 6658.6,7045.41 6727.9,7045.41 6799.35,7045.41 6876.17,7045.41 7603.2,7045.24 7737.1,7044.54 7533.9,7046.41 7667.8,7045.71 6658.6,7114.93 6727.9,7114.93 6799.35,7114.93 6876.17,7114.93 7737.1,7115.18 7603.2,7115.88 7667.8,7116.22 7533.9,7116.92 6658.6,7184.44 6727.9,7184.44 6799.35,7184.44 6876.17,7184.44 7737.1,7185.82 7533.9,7187.43 7603.2,7186.52 7667.8,7186.73 6658.6,7253.95 6727.9,7253.95 6799.35,7253.95 6876.17,7253.95 7737.1,7256.46 7603.2,7257.16 7667.8,7257.24 7533.9,7257.94 6658.6,7323.47 6727.9,7323.47 6799.35,7323.47 6876.17,7323.47 7737.1,7327.1 7533.9,7328.45 7603.2,7327.8 7667.8,7327.75 6658.6,7392.98 6727.9,7392.98 6799.35,7392.98 6876.17,7392.98 7603.2,7398.44 7667.8,7398.26 7737.1,7397.74 7533.9,7398.96 6658.6,7462.49 6727.9,7462.49 6799.35,7462.49 6876.17,7462.49 7737.1,7468.38 7533.9,7469.47 7603.2,7469.08 7667.8,7468.77 6658.6,7532.01 6727.9,7532.01 6799.35,7532.01 6876.17,7532.01 7667.8,7539.28 7737.1,7539.02 7533.9,7539.98 7603.2,7539.72 6658.6,7601.52 6727.9,7601.52 6799.35,7601.52 6876.17,7601.52 7533.9,7610.49 7603.2,7610.36 7667.8,7609.79 7737.1,7609.66 6658.6,7671.03 6727.9,7671.03 6799.35,7671.03 6876.17,7671.03 7667.8,7680.3 7737.1,7680.3 7533.9,7681 7603.2,7681
  other v3: 6984.7,7033.1 7024.7,7033.1 7064.7,7033.1 7364.7,7033.1 7404.7,7033.1 7444.7,7033.1 6984.7,7073.1 7444.7,7073.1 6984.7,7113.1 7444.7,7113.1 6989.7,7548.1 7029.7,7548.1 7069.7,7548.1 7109.7,7548.1 7149.7,7548.1 7189.7,7548.1 7239.7,7548.1 7279.7,7548.1 7319.7,7548.1 7359.7,7548.1 7399.7,7548.1 7439.7,7548.1 6989.7,7588.1 7029.7,7588.1 7069.7,7588.1 7109.7,7588.1 7149.7,7588.1 7189.7,7588.1 7239.7,7588.1 7279.7,7588.1 7319.7,7588.1 7359.7,7588.1 7399.7,7588.1 7439.7,7588.1 6989.7,7628.1 7029.7,7628.1 7069.7,7628.1 7109.7,7628.1 7149.7,7628.1 7189.7,7628.1 7239.7,7628.1 7279.7,7628.1 7319.7,7628.1 7359.7,7628.1 7399.7,7628.1 7439.7,7628.1 6989.7,7668.1 7029.7,7668.1 7069.7,7668.1 7109.7,7668.1 7149.7,7668.1 7189.7,7668.1 7239.7,7668.1 7279.7,7668.1 7319.7,7668.1 7359.7,7668.1 7399.7,7668.1 7439.7,7668.1
  other v4: 6827.7,5035 6871.1,5035 6827.7,5076.8 6871.1,5077.7 7418.5,5571.93 7418.7,5612.13 8088.52,6144.26 8259.65,6144.26 7196.14,6165.3 6710.6,6175.42 7809.56,6176.43 7303.4,6177.14 6540.91,6184.63 8088.52,6193.39 8259.65,6193.39 7196.14,6209.9 7809.56,6219.48 7336.58,6225.8 6710.6,6232.4 6759.2,6232.4 6807.8,6232.4 6540.91,6233.18 6540.91,6281.74 6399.98,6330.29 6446.96,6330.29 6493.93,6330.29 6540.91,6330.29 8015.22,6486.75 8072.94,6486.75 8130.66,6486.75 8188.38,6486.75 8246.1,6486.75 8015.22,6543.9 8072.94,6543.9 8130.66,6543.9 8188.38,6543.9
VINC: C82.2 C83.2 C84.2 C85.2 C86.2 C178.1 C179.1 C180.1 C181.1 C194.1 C195.1 C196.1 C197.1 C210.1 C211.1 C212.1 C213.1 C226.1 C227.1 C228.1 C229.1 C242.1 C243.1 C244.1 C245.1 C258.1 C259.1 C260.1 C261.1 C274.1 C275.1 C276.1 C277.1 C290.1 C291.1 C292.1 C293.1 R129.2 TP16.1 U8.25 U8.26 U8.27 U8.28 U8.29 U8.30 U9.25 U9.26 U9.27 U9.28 U9.29 U9.30 U10.25 U10.26 U10.27 U10.28 U10.29 U10.30 U11.25 U11.26 U11.27 U11.28 U11.29 U11.30 U12.25 U12.26 U12.27 U12.28 U12.29 U12.30 U13.25 U13.26 U13.27 U13.28 U13.29 U13.30 U14.25 U14.26 U14.27 U14.28 U14.29 U14.30 U15.25 U15.26 U15.27 U15.28 U15.29 U15.30 | length 234.3
  Top Layer w6: R129.2@8077.68,5374.14 8077.68,5347.82 8092,5333.5 C82.2@8257.48,5333.5
  Top Layer w15: v5(5382.9,4064.79) 5383.8,4065.69 5402.76,4065.69 5403.52,4066.45 5403.63,4066.35 ; v5(5804.14,4064.79) v5@5804.67,4064.26
  other v1: 7547.9,4489.98 7612.02,4489.98 7676.14,4489.98 7740.26,4489.98 7804.38,4489.98 7868.5,4489.98 7932.62,4489.98 7996.74,4489.98 8060.86,4489.98 8124.98,4489.98 8189.1,4489.98 8253.22,4489.98 8317.34,4489.98 8381.46,4489.98 8445.58,4489.98 7547.9,4549.58 7612.02,4549.58 7676.14,4549.58 7740.26,4549.58 7804.38,4549.58 7868.5,4549.58 7932.62,4549.58 7996.74,4549.58 8060.86,4549.58 8124.98,4549.58 8189.1,4549.58 8253.22,4549.58 8317.34,4549.58 8381.46,4549.58 8445.58,4549.58 7547.9,4609.18 7612.02,4609.18 7676.14,4609.18 7740.26,4609.18 7804.38,4609.18 7868.5,4609.18 7932.62,4609.18 7996.74,4609.18 8060.86,4609.18 8124.98,4609.18 8189.1,4609.18 8253.22,4609.18 8317.34,4609.18 8381.46,4609.18 8445.58,4609.18 7806.79,4664.78 7872.05,4664.78 7937.46,4664.78 8002.58,4664.78 7806.79,4724.37 7872.05,4724.37 7937.46,4724.37 8002.58,4724.37 7806.79,4783.97 7872.05,4783.97 7937.46,4783.97 8002.58,4783.97 7806.79,4843.57 7872.05,4843.57 7937.46,4843.57 8002.58,4843.57 7806.79,4903.17 7872.05,4903.17 7937.46,4903.17 8002.58,4903.17 7806.79,4962.77 7872.05,4962.77 7937.46,4962.77 8002.58,4962.77 7806.79,5022.36 7872.05,5022.36 7937.46,5022.36 8002.58,5022.36 7806.79,5081.96 7872.05,5081.96 7937.46,5081.96 8002.58,5081.96 7806.79,5141.56 7872.05,5141.56 7937.32,5141.56 8002.58,5141.56
  other v2: 5440.22,4112.88 5480.73,4112.88 5511.45,4112.88 6677.94,4116.12 6706.1,4116.4 5848.75,4116.59 5877.22,4116.84 5905.68,4116.84 6264.37,4116.96 6293.22,4116.96 6319.08,4116.87 7093.38,4118.95 7119.56,4118.95 7145.74,4118.95 8396.73,4119.74 8428.39,4119.74 8461.15,4119.74 8491.78,4119.74 7488.81,4121.67 7518.06,4121.98 7545.15,4121.98 7956.09,4121.67 7985.71,4121.67 8015.33,4121.67 8044.95,4121.67 6677.94,4140.98 6706.1,4141.05 5440.22,4144 5868.98,4147.46 5904.7,4147.46 6293.22,4147.12 6319.08,4147.03 7518.06,4147.83 7545.15,4147.83 7985.71,4150.72 8015.33,4150.72 7136.78,4154.65 8432.25,4159.9 8461.15,4159.88 7518.06,4173.68 7545.15,4173.68 7136.78,4182.99
  other v4: 5576.77,4383.85 5577.22,4428.95 5638.93,4428.95 5704.19,4428.95 5769.6,4428.95 5834.73,4428.95 5897.96,4428.95 5963.22,4428.95 6028.63,4428.95 6093.75,4428.95
  other v5: 7872.66,4064.4 7906.13,4064.4 5349.44,4064.79 5770.68,4064.79 6180.83,4064.79 6214.29,4064.79 6595.23,4064.79 6628.69,4064.79 7007.89,4064.79 7041.35,4064.79 7398.58,4064.79 7432.04,4064.79 8315.68,4065.11 8349.15,4065.11 5349.44,4095.31 5382.9,4095.31 5770.68,4095.31 5804.14,4095.31 6180.83,4095.31 6214.29,4095.31 6595.23,4095.3 6628.69,4095.3 7007.89,4095.3 7041.35,4095.3 7398.58,4095.3 7432.04,4095.3 7872.66,4094.91 7906.13,4094.91 8315.68,4095.62 8349.15,4095.62 7872.66,4125.42 7906.13,4125.42 5349.44,4125.82 5382.9,4125.82 5770.68,4125.82 5804.14,4125.82 6180.83,4125.82 6214.29,4125.82 6595.23,4125.82 6628.69,4125.82 7007.89,4125.82 7041.35,4125.82 7398.58,4125.82 7432.04,4125.82 8315.68,4126.14 8349.15,4126.14
VOUT_1: C372.1 C373.1 C374.1 C375.1 C376.1 J34.2 R233.2 TP67.1 U18.20 U18.21 U18.22 U18.23 U18.24 U18.25 U18.26 | length 563.8
  Top Layer w6: R233.2@6956.9,5243.36 6957.41,5242.84 v2(6957.41,5215.44)
  Singal 3 w6: v1(6513.63,5073.97) 6768.83,5073.97 6824.69,5129.84 6928.71,5129.84 6957.41,5158.54 v2(6957.41,5215.44)
  other v1: 6384.67,5073.97 6448.93,5073.97 6384.67,5129.84 6448.93,5129.84 6513.63,5129.84 6384.67,5185.7 6448.93,5185.7 6513.63,5185.7
VOUT_2: C377.1 C378.1 C379.1 C380.1 C381.1 J35.2 R236.2 TP69.1 U18.13 U18.14 U18.15 U18.16 U18.17 U18.18 U18.19 | length 742.4
  Top Layer w6: R236.2@6956.9,5399 6956.9,5415.45 v2(6974.96,5433.51)
  Singal 3 w6: v1(6516.5,5580.17) 6587.43,5651.1 6928.71,5651.1 6967.68,5612.13 7001.62,5578.2 7001.62,5460.17 v2(6974.96,5433.51)
  other v1: 6390.49,5479.67 6455.78,5479.67 6516.5,5479.67 6455.78,5527.94 6516.5,5527.94 6390.49,5530.53 6390.49,5580.17 6455.78,5580.17
VOUT_3: C385.1 C386.1 C390.1 C391.1 C392.1 J36.2 R240.2 TP80.1 U19.20 U19.21 U19.22 U19.23 U19.24 U19.25 U19.26 | length 28.7
  Top Layer w6: R240.2@7655.43,6314.24 v2(7684.15,6314.24)
  other v1: 7724.18,5748.01 7778.94,5748.08 7724.18,5796.91 7778.94,5796.98 7724.18,5845.8 7778.94,5845.87 7724.18,5894.7 7778.94,5894.77
VOUT_4: C387.1 C388.1 C393.1 C394.1 C395.1 J37.2 R243.2 TP82.1 U19.13 U19.14 U19.15 U19.16 U19.17 U19.18 U19.19 | length 28.7
  Top Layer w6: v2(7387.16,6314.14) R243.2@7415.88,6314.14
  other v1: 7318.77,5747.94 7373.53,5748.01 7318.77,5796.83 7373.53,5796.91 7318.77,5845.73 7373.53,5845.8 7318.77,5894.62 7373.53,5894.7
VOUT_A_RDY: R34.1 R133.1 R143.2 TP29.1 U3.12 | length 2787.4
  Top Layer w6: R143.2@4383.34,4265.65 R133.1@4383.34,4203.06 v4(4466.87,4203.06) v4@4470.6,4206.79 ; R34.1@6432.74,4793.38 6461.86,4793.38 6473.09,4804.61 v2(6476.08,4804.61) 6479.07,4804.61 6490.3,4793.38 U3.12@6515.65,4793.38
  Singal 3 w6: v4(4466.87,4203.06) 4466.87,4110.23 4494.3,4082.8 TP29.1@4586.47,4082.8 4586.47,4140.25 4961.21,4514.99 6318.03,4514.99 6454.62,4651.58 6454.62,4712.26 6501.01,4758.65 6501.01,4779.69 v2(6476.08,4804.61)
VOUT_B_RDY: R35.1 R135.1 R140.2 TP30.1 U3.16 | length 2764.9
  Top Layer w6: R140.2@4383.39,4041.37 R135.1@4383.39,3979.13 4433.31,3979.13 v4(4470.6,4016.42) ; R35.1@6450.49,4714.2 6451.44,4715.15 6481.55,4715.15 6496.58,4730.18 U3.16@6515.43,4730.18
  Singal 3 w6: v4(4470.6,4016.42) 4470.6,3960.8 4508.24,3923.16 4583.51,3923.16 TP30.1@4586.47,3920.2 4643.61,3977.34 4643.61,4092.36 5046.32,4495.07 6341.8,4495.07 6482.17,4635.44 6482.17,4715.77 v2(6482.5,4716.1)
VR_FAULT#: R36.1 R136.1 R139.2 TP28.1 U3.33 | length 3125.5
  Top Layer w6: R136.1@4382.17,3730.86 4383.39,3732.07 R139.2@4383.39,3802.81 4432.18,3802.81 v4(4470.6,3841.23) ; U3.33@6704.62,4698.89 6725.14,4698.89 6748.45,4675.58 6753.12,4675.58 v2(6755.41,4673.29)
  Singal 3 w6: v4(4470.6,3841.23) 4470.6,3791.93 4494.3,3768.23 4586.47,3768.23 4700.5,3882.26 4700.5,4060.9 5120.3,4480.7 6363.24,4480.7 6529.14,4646.6 6728.73,4646.6 v2(6755.41,4673.29)
  Bottom Layer w6: v2(6755.41,4673.29) 6757.71,4670.99 6757.71,4657.92 6770.67,4644.96 R36.1@6801.08,4644.96
VREF: C182.2 C199.2 C216.2 C230.2 C248.2 C264.2 C278.2 C295.2 J32.1 J38.1 J39.1 J40.1 J41.1 J42.1 J43.1 J44.1 R14.1 R17.2 R18.1 U8.39 U9.39 U10.39 U11.39 U12.39 U13.39 U14.39 U15.39 | length 25234.6
  Top Layer w6: v2(6827.32,4208.03) 6827.19,4207.91 6827.19,4177.2 C248.2@6827.07,4177.08 6845.54,4177.08 6863.33,4159.28 U12.39@6883.87,4159.28 ; v2(7201.49,4207.22) 7219.02,4207.22 7222.54,4203.71 7222.54,4186.95 C264.2@7223.28,4186.21 7226.09,4183.4 7226.09,4168.79 7235.6,4159.28 U13.39@7274.56,4159.28
  Top Layer w10: v2(5127.1,4210.77) 5128.66,4209.21 5145.59,4209.21 5149.1,4205.69 C182.2@5149.1,4177 5187.2,4177 5204.92,4159.28 U8.39@5225.42,4159.28 ; v2(5578.74,4206.55) 5578.74,4204.39 5586.64,4196.49 5586.64,4182.43 C199.2@5589.07,4180 ; C199.2@5589.14,4179.93 5607.2,4179.93 5627.84,4159.28 U9.39@5646.66,4159.28 ; v2(6013.94,4219.05) 6013.94,4185.93 6016.44,4183.43 6022.69,4183.43 6042.04,4164.09 6054.92,4164.09 6056.81,4162.2 U10.39@6056.81,4159.28 ; v2(6424.32,4242.59) 6424.08,4242.35 6424.08,4205.4 C230.2@6423.84,4205.16 6423.84,4184.04 6448.6,4159.28 U11.39@6471.21,4159.28 ; v2(7642.32,4220.47) 7643.85,4218.94 7654.69,4218.94 7680.57,4193.06 7680.81,4193.06 7685.81,4188.06 7685.81,4179.06 7694.07,4179.06 7714.24,4158.89 U14.39@7748.65,4158.89 ; v2(8111.2,4207.4) 8112.73,4205.87 8112.73,4201.22 8128.13,4185.82 8128.13,4183.47 8130.16,4181.44 8155.03,4181.44 8169.78,4166.69 8189.78,4166.69 8191.23,4165.24 U15.39@8191.23,4158.89
  Signal 1 w6: v2(7642.32,4220.47) 7657.37,4205.41 7683.14,4205.41 7699.56,4221.83 7713.64,4221.83 7719.64,4215.83 7749.17,4215.83 7787.14,4253.8 9864.76,4253.8 9987.46,4131.1 10340.74,4131.1 10571.17,4361.53 J43.1@10571.2,4405.1
  Power 3 w6: J38.1@3895.7,2973.7 3940.3,2929.1 4016.62,2929.1 4050.22,2962.7 4311.7,2962.7 4899.3,3550.3 4899.3,4107.86 5035.34,4243.9 5561.11,4243.9 5578.74,4226.26 v2(5578.74,4206.55) ; J39.1@3895.7,3107.9 3940.8,3062.8 4018.5,3062.8 4052.6,3096.9 4372.2,3096.9 4785.1,3509.8 4785.1,4058.7 5043.5,4317.1 5604.11,4317.1 5650.51,4363.5 5904.47,4363.5 6013.94,4254.03 v2(6013.94,4219.05) ; J32.1@3895.77,2839.43 3945.2,2790 4023.5,2790 4062,2828.5 4248.5,2828.5 4942.1,3522.1 4942.1,4099.6 5064.24,4221.74 5112.88,4221.74 5123.85,4210.77 v2(5127.1,4210.77) ; v2(6424.32,4242.59) 6424.32,4243.11 6411.85,4255.58 6411.85,4307.67 6530.81,4426.64 10126.49,4426.64 10130,4430.15 J40.1@10130,4477 ; v2(6827.32,4208.03) 6860.1,4240.82 6860.1,4352.66 6909.78,4402.33 10115.67,4402.33 10130,4388 J41.1@10130,4344 ; v2(7201.49,4207.22) 7201.49,4341.74 7240.08,4380.33 9729.97,4380.33 9904.4,4205.9 J42.1@10141,4205.9 ; v2(8111.2,4207.4) 8163.23,4207.4 8197.5,4241.67 8205.98,4241.67 8216.98,4252.67 9361.49,4252.67 9498.06,4116.1 10565.84,4116.1 10571.2,4121.46 J44.1@10571.2,4205.9
  Bottom Layer w6: v2(6385.74,4689.59) R18.1@6421.33,4689.59
  Bottom Layer w10: R14.1@6836.07,4767.9 6843.57,4767.9 6883.87,4808.21 6883.87,4846.61 v2(6868.12,4862.36)
  other v2: 6845.08,4862.36
VSN_VOUT_A: C10.2 C14.1 J5.1 J9.122 R9.1 R15.2 | length 6477.8
  Top Layer w6: v2(6479.53,4459.42) 6479.44,4459.52 6479.44,4488.71 C10.2@6479.35,4488.8 6479.35,4526.06 R9.1@6479.67,4526.38 ; v2(6913.84,2125.46) 6913.84,2155.83 6918.34,2160.33 6922.84,2160.33 6927.7,2165.19 6927.7,2247.7 6913.84,2261.56 J9.122@6913.84,2370.22
  Signal 1 w6: J5.1@3624.1,5364 3676,5415.9 3795.96,5415.9 4163.26,5048.6 4224.06,4987.8 6136.3,4987.8 6171.6,4952.5 6171.6,4559.86 6244.94,4486.51 6452.45,4486.51 v2(6479.53,4459.42)
  Signal 2 w6: v2(6479.53,4459.42) 6502.74,4436.22 6568.46,4436.22 6765.79,4238.89 6765.79,4132.56 6785.22,4113.13 6785.22,2660.18 6789.51,2655.9 6921.3,2655.9 6936.8,2640.4 6936.8,2148.42 v2(6913.84,2125.46)
VSN_VOUT_B: C12.2 C15.1 J6.1 J10.122 R12.1 R16.2 | length 9779.5
  Top Layer w6: R12.1@6754.52,4526.38 6756.79,4524.11 C12.2@6756.79,4489.62 6756.98,4489.43 6756.98,4456.08 v2(6757.17,4455.89) ; J10.122@10641.01,3113.18 10641.01,3099.94 10647.85,3093.1 v2(10760.77,3093.1) 10797.54,3056.33 R16.2@10840.47,3056.33 10879.96,3056.33 10883.47,3052.82 C15.1@10883.47,3036.33
  Signal 2 w6: v2(6757.17,4455.89) 6759.47,4453.59 6759.47,4393.6 6913.17,4239.89 7563.35,4239.89 7598.4,4204.84 7598.4,4129.42 7619.5,4108.33 7619.5,3636.4 7583.7,3600.6 7583.7,2771.2 7611.8,2743.1 9104.46,2743.1 9415.11,3053.76 10721.42,3053.76 v2(10760.77,3093.1)
  Singal 3 w6: J6.1@3725.54,5494.2 3778.4,5494.2 4301.6,4971 6137.74,4971 6161.3,4947.44 6161.3,4654.31 6236.31,4579.3 v2(6261.59,4579.3)
  Bottom Layer w6: v2(6261.59,4579.3) 6293.39,4547.5 6685.29,4547.5 6757.17,4475.62 v2(6757.17,4455.89)
VSP_VOUT_A: C10.1 C11.1 J5.2 J9.121 R7.1 R8.1 | length 5792.4
  Top Layer w6: v2(6440.11,4459.42) 6439.73,4459.8 6439.73,4488.42 C10.1@6439.35,4488.8 6439.35,4525.63 R7.1@6440.11,4526.38 ; v2(6913.4,2631.8) 6913.4,2504.52 J9.121@6913.84,2504.08
  Signal 1 w6: J5.2@3724.1,5364 3786.44,5364 4178.24,4972.2 6136.34,4972.2 6160.6,4947.94 6160.6,4555.3 6240.39,4475.51 6424.02,4475.51 v2(6440.11,4459.42)
  Signal 2 w6: v2(6440.11,4459.42) 6474.31,4425.22 6563.9,4425.22 6754.79,4234.33 6754.79,4128 6774.22,4108.57 6774.22,2655.62 6798.05,2631.8 v2(6913.4,2631.8)
  Bottom Layer w6: R8.1@6913.4,2587.4 6913.5,2587.3 6960.2,2587.3 C11.1@6964.5,2587.3 6964.5,2607.5 6940.2,2631.8 v2(6913.4,2631.8)
VSP_VOUT_B: C12.1 C13.1 J6.2 J10.121 R10.1 R11.1 | length 9862.9
  Top Layer w6: v2(6796.79,4455.89) C12.1@6796.79,4489.62 6796.79,4524.74 R11.1@6798.43,4526.38 ; J10.121@10641.01,3247.04 10641.24,3247.27 R10.1@10641.24,3387.33 ; v2(10641.24,3433.66) R10.1@10641.24,3387.33 ; C13.1@10681.64,3387.33 R10.1@10641.24,3387.33
  Signal 2 w6: v2(6796.79,4455.89) 6796.79,4371.83 6917.73,4250.89 7567.9,4250.89 7609.4,4209.39 7609.4,4133.98 7630.5,4112.88 7630.5,3631.84 7594.7,3596.04 7594.7,2775.76 7616.36,2754.1 9099.9,2754.1 9410.56,3064.76 9618.83,3273.03 10480.61,3273.03 v2(10641.24,3433.66)
  Singal 3 w6: J6.2@3625.54,5494.2 3677.94,5546.6 3800.8,5546.6 3800.8,5545.3 4359.9,4986.2 6138.1,4986.2 6172.3,4952 6172.3,4677.2 6241.66,4607.84 v2(6261.59,4607.84)
  Bottom Layer w6: v2(6261.59,4607.84) 6310.42,4559 6693.68,4559 v2(6796.79,4455.89)
VTT: C345.1 C397.1 J30.1 TP71.1 U16.47 U16.48
  other v2: 6064.35,5459.81 6087.55,5459.81
pads on no net: D7.2 H1.1 H2.0 H3.1 H4.0 H5.1 H6.0 H7.1 H8.0 J7.1 J7.2 J7.3 J7.4 J7.5 J7.7 J9.61 J9.62 J10.61 J10.62 J26.1 J26.2 J26.3 J26.4 J26.5 J26.7 J26.8 Q1.9@4302.5,1798.45 Q1.9@4302.5,1854.75 Q1.9@4302.5,1911.05 Q1.9@4355.26,1798.45 Q1.9@4355.26,1854.75 Q1.9@4355.26,1911.05 Q1.9@4359.2,1854.75 Q1.9@4408.02,1798.45 Q1.9@4408.02,1854.75 Q1.9@4408.02,1911.05 Q2.9@4302.5,2009.73 Q2.9@4302.5,2066.03 Q2.9@4302.5,2122.33 Q2.9@4355.26,2009.73 Q2.9@4355.26,2066.03 Q2.9@4355.26,2122.33 Q2.9@4359.2,2066.03 Q2.9@4408.02,2009.73 Q2.9@4408.02,2066.03 Q2.9@4408.02,2122.33 Q3.9@8352.87,1977.41 Q3.9@8352.87,2033.71 Q3.9@8352.87,2090.01 Q3.9@8401.69,2033.71 Q3.9@8405.63,1977.41 Q3.9@8405.63,2033.71 Q3.9@8405.63,2090.01 Q3.9@8458.38,1977.41 Q3.9@8458.38,2033.71 Q3.9@8458.38,2090.01 Q4.9@8352.87,1753.01 Q4.9@8352.87,1809.31 Q4.9@8352.87,1865.6 Q4.9@8401.69,1809.31 Q4.9@8405.63,1753.01 Q4.9@8405.63,1809.31 Q4.9@8405.63,1865.6 Q4.9@8458.38,1753.01 Q4.9@8458.38,1809.31 Q4.9@8458.38,1865.6 S1.3 S2.3 U2.0 U2.7 U3.17 U3.18 U3.19 U3.41@6579.23,4707.36 U3.41@6579.23,4769.17 U3.41@6641.04,4707.36 U3.41@6641.04,4769.17 U5.1 U5.8 U7.1 U7.8 U8.6 U8.24@5245.11,3985.86 U8.24@5284.48,3977.79 U8.24@5284.48,4021.88 U8.24@5323.85,3977.79 U8.24@5323.85,4021.88 U8.24@5363.22,3977.79 U8.24@5363.22,4021.88 U8.31 U8.40@5252.19,4074.24 U8.40@5252.19,4116.37 U8.40@5287.23,4074.24 U8.40@5287.23,4116.37 U8.40@5333.1,4074.24 U8.40@5333.1,4116.37 U8.40@5366.17,4074.24 U8.40@5366.17,4116.37 U8.41 U9.6 U9.24@5666.35,3985.86 U9.24@5705.72,3977.79 U9.24@5705.72,4021.88 U9.24@5745.09,3977.79 U9.24@5745.09,4021.88 U9.24@5784.46,3977.79 U9.24@5784.46,4021.88 U9.31 U9.40@5673.43,4074.24 U9.40@5673.43,4116.37 U9.40@5708.47,4074.24 U9.40@5708.47,4116.37 U9.40@5754.34,4074.24 U9.40@5754.34,4116.37 U9.40@5787.41,4074.24 U9.40@5787.41,4116.37 U9.41 U10.6 U10.24@6076.5,3985.86 U10.24@6115.87,3977.79 U10.24@6115.87,4021.88 U10.24@6155.24,3977.79 U10.24@6155.24,4021.88 U10.24@6194.61,3977.79 U10.24@6194.61,4021.88 U10.31 U10.40@6083.59,4074.24 U10.40@6083.59,4116.37 U10.40@6118.62,4074.24 U10.40@6118.62,4116.37 U10.40@6164.49,4074.24 U10.40@6164.49,4116.37 U10.40@6197.56,4074.24 U10.40@6197.56,4116.37 U10.41 U11.6 U11.24@6490.9,3985.86 U11.24@6530.27,3977.79 U11.24@6530.27,4021.88 U11.24@6569.64,3977.79 U11.24@6569.64,4021.88 U11.24@6609.01,3977.79 U11.24@6609.01,4021.88 U11.31 U11.40@6497.98,4074.24 U11.40@6497.98,4116.37 U11.40@6533.02,4074.24 U11.40@6533.02,4116.37 U11.40@6578.89,4074.24 U11.40@6578.89,4116.37 U11.40@6611.96,4074.24 U11.40@6611.96,4116.37 U11.41 U12.6 U12.24@6903.56,3985.86 U12.24@6942.93,3977.79 U12.24@6942.93,4021.88 U12.24@6982.3,3977.79 U12.24@6982.3,4021.88 U12.24@7021.67,3977.79 U12.24@7021.67,4021.88 U12.31 U12.40@6910.64,4074.24 U12.40@6910.64,4116.37 U12.40@6945.68,4074.24 U12.40@6945.68,4116.37 U12.40@6991.55,4074.24 U12.40@6991.55,4116.37 U12.40@7024.62,4074.24 U12.40@7024.62,4116.37 U12.41 U13.6 U13.24@7294.25,3985.86 U13.24@7333.62,3977.79 U13.24@7333.62,4021.88 U13.24@7372.99,3977.79 U13.24@7372.99,4021.88 U13.24@7412.36,3977.79 U13.24@7412.36,4021.88 U13.31 U13.40@7301.33,4074.24 U13.40@7301.33,4116.37 U13.40@7336.37,4074.24 U13.40@7336.37,4116.37 U13.40@7382.24,4074.24 U13.40@7382.24,4116.37 U13.40@7415.31,4074.24 U13.40@7415.31,4116.37 U13.41 U14.6 U14.24@7768.33,3985.46 U14.24@7807.7,3977.39 U14.24@7807.7,4021.49 U14.24@7847.07,3977.39 U14.24@7847.07,4021.49 U14.24@7886.44,3977.39 U14.24@7886.44,4021.49 U14.31 U14.40@7775.42,4073.85 U14.40@7775.42,4115.98 U14.40@7810.46,4073.85 U14.40@7810.46,4115.98 U14.40@7856.32,4073.85 U14.40@7856.32,4115.98 U14.40@7889.39,4073.85 U14.40@7889.39,4115.98 U14.41 U15.6 U15.24@8211.35,3986.18 U15.24@8250.72,3978.1 U15.24@8250.72,4022.2 U15.24@8290.09,3978.1 U15.24@8290.09,4022.2 U15.24@8329.46,3978.1 U15.24@8329.46,4022.2 U15.31 U15.40@8218.44,4074.56 U15.40@8218.44,4116.69 U15.40@8253.48,4074.56 U15.40@8253.48,4116.69 U15.40@8299.34,4074.56 U15.40@8299.34,4116.69 U15.40@8332.42,4074.56 U15.40@8332.42,4116.69 U15.41 U17.2 U17.3 U17.7 U17.8 U17.9 U17.30 U17.31 U17.32 U17.36 U17.39 U17.45 U17.46 U18.2 U18.3 U18.7 U18.8 U18.9 U18.30 U18.31 U18.32 U18.36 U19.2 U19.3 U19.7 U19.8 U19.9 U19.30 U19.31 U19.32 U19.36

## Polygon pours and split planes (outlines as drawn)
5V-AUX on Bottom Layer "BOTTOM_LAYER_5V-AUX_P079" (solid, pour order 79): 21 vertices, not listed, extent 7107.5,5128.07 7207.19,5353.91
3V3-LDO on Bottom Layer "BOTTOM_LAYER_3V3-LDO_P082" (solid, pour order 82): 7128.19,5072.28 7130.73,5074.82 7187.73,5074.82 7191.53,5071.02 7191.53,4938.78 7187.69,4934.95 7132.94,4934.95 7128.19,4939.69
3.3V-Con on Bottom Layer "BOTTOM_LAYER_3.3V-CON_P083" (solid, pour order 83): 7068.17,4908.95 7072.43,4913.22 7179.62,4913.22 7183.86,4908.98 7183.86,4846.11 7179.94,4842.19 7076.32,4842.19 7068.22,4850.3
VINC on Bottom Layer "BOTTOM_LAYER_VINC_P075" (solid, pour order 75): 105 vertices, not listed, extent 5310.58,4049.42 8511.43,5404.5
VIN on Bottom Layer "BOTTOM_LAYER_VIN_P196" (solid, pour order 196): 52 vertices, not listed, extent 5662.9,5015.46 8354.9,7725.04
GND on Bottom Layer "BOTTOM_LAYER_GND_P230" (solid, pour order 230): 9508.5,3112.9 9556.24,3160.63 10604.64,3160.63 10624.44,3140.83 10624.44,3022.13 10631.84,3014.73 10861.64,3014.73 10873.54,3002.83 10873.54,2917.32 10857.85,2901.63 9514.94,2901.63 9508.5,2908.07
GND on Bottom Layer "BOTTOM_LAYER_GND_P227" (solid, pour order 227): 49.1,7702 70,7722.9 11155.9,7722.9 11174.4,7704.4 11168.51,7698.51 11168.51,107.92 11132.03,71.43 11131.56,71.9 93.47,71.43 49.1,115.8
GND on Bottom Layer "BOTTOM_LAYER_GND_P166" (solid, pour order 166): 7419.06,3231.51 7424.57,3237.01 7553.06,3237.01 7597.88,3192.19 7597.88,2768.18 7588.7,2759 7426.42,2759 7419.06,2765.84
BUCK1_OUT on Bottom Layer "BOTTOM_LAYER_BUCK1_OUT_P131" (solid, pour order 131): 3052,70.7 3961.1,70.7 3999,108.6 3999,2679.02 4893.7,3573.72 4893.7,4296.4 5156.3,4559 5537.79,4559 5574.3,4595.51 5574.3,4822.7 5546.7,4850.3 3236.2,4850.3 2982.45,4596.56 2982.45,140.25
BUCK6_OUT on Bottom Layer "BOTTOM_LAYER_BUCK6_OUT_P132" (solid, pour order 132): 18 vertices, not listed, extent 2106.9,67.9 6017.35,5198.9
NetQ2_5 on Bottom Layer "BOTTOM_LAYER_NETQ2_5_P142" (solid, pour order 142): 4048.5,2479.92 4060.03,2491.46 5154.22,2491.46 5168.6,2477.08 5168.6,1204.52 5159.63,1195.56 4060.52,1195.56 4048.5,1207.58
NetQ4_5 on Bottom Layer "BOTTOM_LAYER_NETQ4_5_P155" (solid, pour order 155): 8775.87,1207.09 8764.34,1195.56 7670.15,1195.56 7655.77,1209.93 7655.77,2482.49 7664.74,2491.46 8763.85,2491.46 8775.87,2479.43
PVOUT_B on Bottom Layer "BOTTOM_LAYER_PVOUT_B_P161" (solid, pour order 161): 11071.25,3595.42 7678.5,3595.42 7606.48,3523.4 7606.48,2828.26 7749.31,2685.43 9183.74,2685.43 9900.61,1968.57 9900.61,111.27 9943.99,67.88 11121.19,67.88 11165.99,112.68 11165.99,3500.68
PVOUT_A on Bottom Layer "BOTTOM_LAYER_PVOUT_A_P168" (solid, pour order 168): 4043.8,2584.6 5043.1,3583.9 7495.46,3583.9 7562.88,3516.49 7562.88,2853.22 7756.1,2660 8774.33,2660 8778.67,2655.66 8778.67,94.47 8756.1,71.9 4082.27,71.9 4043.8,110.37
NetL1_2 on Bottom Layer "BOTTOM_LAYER_NETL1_2_P197" (solid, pour order 197): 7893.89,6048.15 7917.73,6071.99 8514.11,6071.99 8541.2,6044.9 8541.2,5429.2 8527.8,5415.8 8124.1,5415.8 7909.7,5415.8 7893.89,5431.61
BUCK2_OUT on Bottom Layer "BOTTOM_LAYER_BUCK2_OUT_P184" (solid, pour order 184): 1112.2,6468.3 5581.9,6468.3 5594,6456.2 5594,6167.5 5580.8,6154.3 3981.5,6154.3 3623.3,5796.1 1900.8,5796.1 1215.1,5110.4 1215.1,1756.3 800.1,1341.3 263.5,1341.3 206.7,1398.1 206.7,5562.8
BUCK3_OUT on Bottom Layer "BOTTOM_LAYER_BUCK3_OUT_P183" (solid, pour order 183): 21 vertices, not listed, extent 201.3,460.9 5807.66,6103.8
GND on Bottom Layer "BOTTOM_LAYER_GND_P160" (solid, pour order 160): 8406,3246.1 8411.5,3251.6 8540,3251.6 8549.78,3241.82 8549.78,2854.18 8538.38,2842.79 8415.57,2842.79 8406,2851.69
GND on Bottom Layer "BOTTOM_LAYER_GND_P152" (solid, pour order 152): 7849.66,3422.79 7857.36,3430.49 8158.51,3430.49 8165.25,3423.74 8165.25,3296.64 8113.02,3244.42 8113.02,2862.1 8093.71,2842.79 7915.43,2842.79 7899.1,2859.12 7899.1,3251.6 7849.66,3301.04
GND on Bottom Layer "BOTTOM_LAYER_GND_P151" (solid, pour order 151): 17 vertices, not listed, extent 5981.3,1081.7 6897,2402.4
GND on Bottom Layer "BOTTOM_LAYER_GND_P148" (solid, pour order 148): 6852.22,3403.64 6859.92,3411.34 7161.06,3411.34 7167.8,3404.6 7167.8,3260.33 7115.58,3208.1 7115.58,2751.63 7096.98,2733.04 6895.38,2733.04 6883.62,2744.81 6883.62,3205.84 6852.22,3237.24
GND on Bottom Layer "BOTTOM_LAYER_GND_P146" (solid, pour order 146): 6031.04,3408.71 6038.73,3416.4 6330.73,3416.4 6335.53,3411.6 6335.53,3254.3 6294.39,3213.16 6294.39,2756.69 6275.8,2738.1 6074.2,2738.1 6062.43,2749.87 6062.43,3210.9 6031.04,3242.3
GND on Bottom Layer "BOTTOM_LAYER_GND_P144" (solid, pour order 144): 5204.7,3408.7 5212.4,3416.4 5504.4,3416.4 5509.2,3411.6 5509.2,3254.3 5468.06,3213.16 5468.06,2685.66 5458.5,2676.1 5243.7,2676.1 5236.1,2683.7 5236.1,3210.9 5204.7,3242.3
5V-DRV on Bottom Layer "BOTTOM_LAYER_5V-DRV_P080" (solid, pour order 80): 7215.23,5348.91 7220.22,5353.9 7286.96,5353.9 7290.82,5350.04 7290.82,5265.95 7284.81,5259.94 7223.52,5259.94 7215.23,5268.23
VIN on Bottom Layer "BOTTOM_LAYER_VIN_P078" (solid, pour order 78): 7262.29,5602.61 7262.29,5588.45 7265.81,5584.93 7290.01,5584.93 7298.75,5576.19 7365.61,5576.19 7389.65,5552.15 7434.55,5552.15 7440.8,5558.4 7440.8,5624.5 7436.08,5629.22 7311.4,5629.22 7288.11,5605.93 7265.61,5605.93
5V_INT on Bottom Layer "BOTTOM_LAYER_5V_INT_P009" (solid, remove dead copper, pour order 9): 7077.92,5384.18 7086.2,5375.9 7328.7,5375.9 7340.8,5388 7340.8,5546.76 7333.48,5554.08 7086.58,5554.08 7077.92,5545.42
NetL10_1 on Top Layer "TOP_LAYER_NETL10_1_P121" (solid, pour order 121): 5875.13,5186.8 5877.63,5189.3 5994.73,5189.3 6013.73,5170.3 6013.73,5043.23 6010.15,5039.65 5790.93,5039.65 5786.33,5044.25 5786.33,5103.7 5792.43,5109.8 5829.93,5109.8 5875.13,5155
